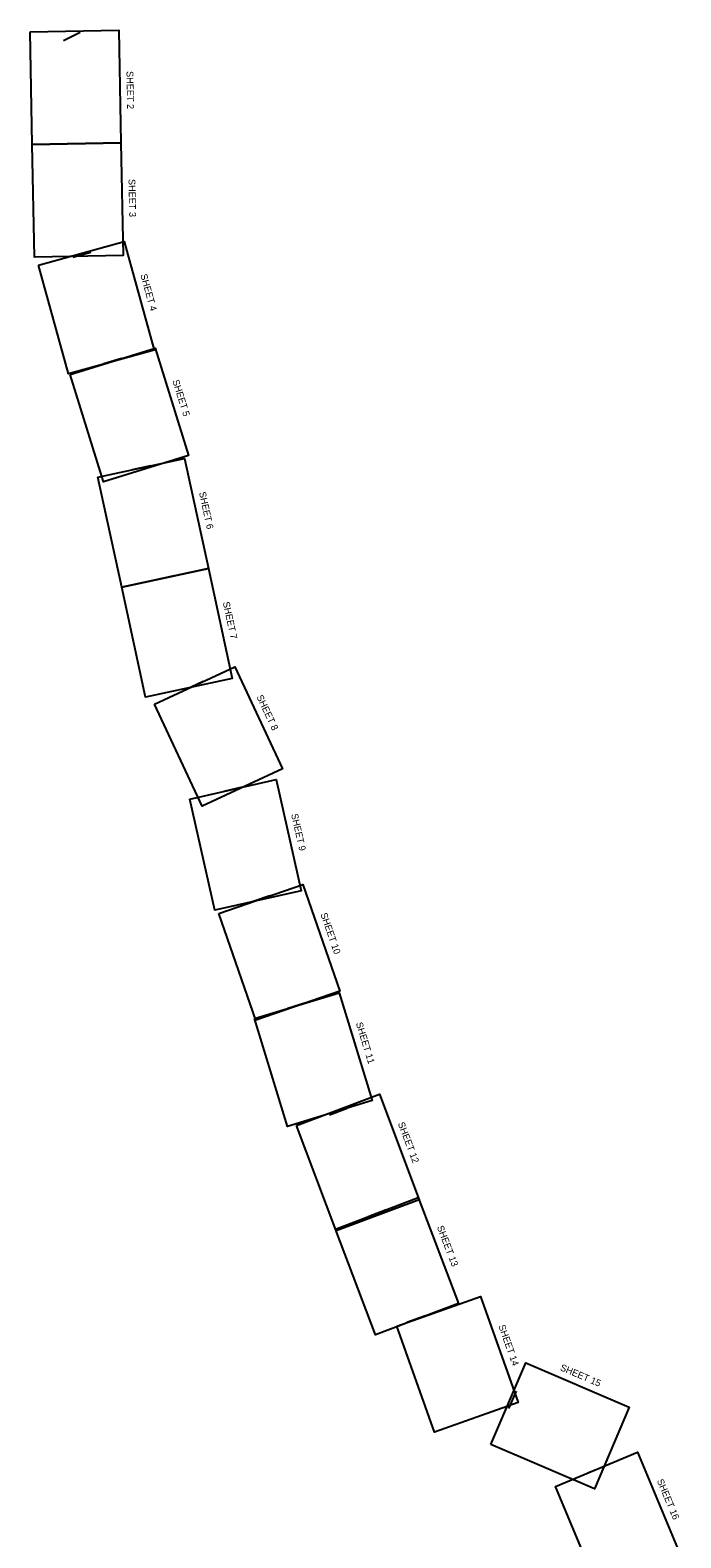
# Model space of a CAD drawing. Extents: x 585633 to 623435, y 1850221 to 1940301.
# Drawn here: x 585633 to 604705, y 1896122 to 1940301 of the extents above; entities that cross this region are included whole.
import ezdxf

# ---------------------------------------------------------------- set-up
doc = ezdxf.new("R2010")
doc.units = 0
for name, color, linetype in [('C-CHAN-LIMT-HIST', 7, 'Continuous'), ('V-ANNO-DIMS', 7, 'Continuous'), ('V-CHAN-CNTR-IDEN', 7, 'Continuous')]:
    doc.layers.add(name, color=color, linetype=linetype)

msp = doc.modelspace()

# ---------------------------------------------------------------- linework, layer by layer
at = {"layer": 'V-ANNO-DIMS'}
for p, q in [((587099, 1940235), (586607, 1939990)), ((587271, 1936982), (586721, 1936972)), ((587410, 1933783), (586880, 1933636)), ((588314, 1930682), (587789, 1930519)), ((589160, 1927537), (588622, 1927421)), ((589856, 1924312), (589319, 1924196)), ((590701, 1921214), (590203, 1920981)), ((591847, 1918116), (591311, 1917996)), ((592657, 1914936), (592137, 1914756)), ((593713, 1911797), (593187, 1911636)), ((594926, 1908701), (594411, 1908507)), ((596051, 1905726), (595537, 1905530)), ((597190, 1902614), (596671, 1902430)), ((599875, 1900421), (599658, 1899915)), ((601979, 1898025), (602486, 1898237))]:
    msp.add_line(p, q, dxfattribs=at)
at = {"layer": 'V-CHAN-CNTR-IDEN'}
for points in [[(585633, 1940251), (588233, 1940301), (588296, 1937002), (585696, 1936952)], [(585696, 1936952), (588296, 1937002), (588359, 1933702), (585759, 1933653)], [(585879, 1933411), (588385, 1934105), (589266, 1930924), (586760, 1930230)], [(586810, 1930215), (589293, 1930986), (590271, 1927834), (587788, 1927063)], [(587620, 1927205), (590162, 1927754), (590858, 1924528), (588317, 1923979)], [(588317, 1923979), (590858, 1924528), (591555, 1921303), (589014, 1920754)], [(589275, 1920546), (591629, 1921649), (593029, 1918660), (590674, 1917558)], [(590311, 1917771), (592847, 1918341), (593580, 1915082), (591043, 1914512)], [(591168, 1914420), (593625, 1915271), (594709, 1912143), (592252, 1911292)], [(592207, 1911336), (594693, 1912097), (595660, 1908942), (593174, 1908180)], [(593438, 1908205), (595872, 1909120), (597033, 1906031), (594599, 1905116)], [(594579, 1905166), (597009, 1906091), (598189, 1902993), (595759, 1902067)], [(596384, 1902329), (598835, 1903198), (599938, 1900088), (597488, 1899218)], [(599138, 1898856), (600162, 1901246), (603195, 1899947), (602172, 1897557)], [(604705, 1895588), (602306, 1894585), (601033, 1897630), (603432, 1898633)]]:
    msp.add_lwpolyline(points, close=True, dxfattribs=at)

# ---------------------------------------------------------------- texts
at = {"layer": 'C-CHAN-LIMT-HIST'}
for s, rotation, p in [('SHEET 2', 271.0925, (588456, 1939100)), ('SHEET 3', 271.0925, (588516, 1935938)), ('SHEET 4', 285.4819, (588863, 1933128)), ('SHEET 5', 287.2521, (589800, 1930028)), ('SHEET 6', 282.1875, (590582, 1926754)), ('SHEET 7', 282.1875, (591278, 1923532)), ('SHEET 8', 295.0848, (592263, 1920768)), ('SHEET 9', 282.6635, (593281, 1917323)), ('SHEET 10', 289.1077, (594139, 1914398)), ('SHEET 11', 287.0343, (595178, 1911199)), ('SHEET 12', 290.6017, (596407, 1908264)), ('SHEET 13', 290.8442, (597551, 1905230)), ('SHEET 14', 289.534, (599355, 1902330)), ('SHEET 15', 336.8189, (601148, 1901041)), ('SHEET 16', 292.6922, (603998, 1897798))]:
    msp.add_text(s, height=200, rotation=rotation, dxfattribs=at).set_placement(p)

doc.saveas('drawing.dxf')
